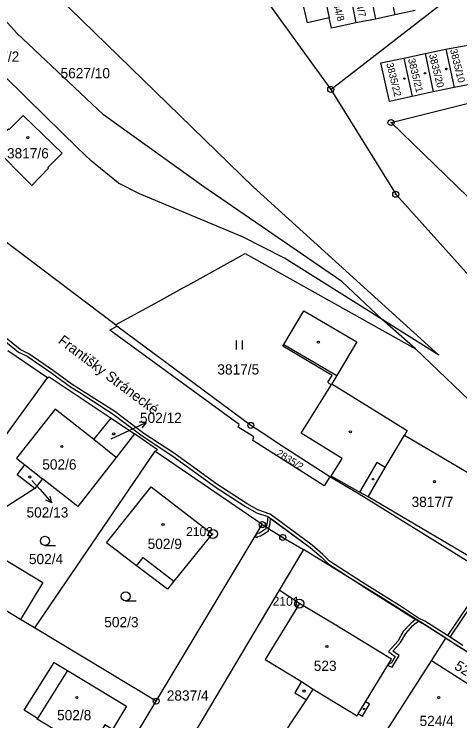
# Model space of a CAD drawing. Extents: x -644096 to -634268, y -1141430 to -1133463.
# Drawn here: x -640437.2 to -640363, y -1137748.7 to -1137631.3 of the extents above; entities that cross this region are included whole.
import ezdxf

# ---------------------------------------------------------------- set-up
doc = ezdxf.new("R2010")
doc.units = 0
for name, color, linetype in [('_CIVIL_CONSTRUCTION', 7, 'Continuous'), ('B_Hranice _3D', 7, 'Continuous'), ('M_Svah_Nasyp', 7, 'Continuous'), ('M_Svah_Zarez', 7, 'Continuous'), ('svrsek_osa_sjezdy', 7, 'Continuous'), ('svrsek_osa_VRT', 7, 'Continuous'), ('svrsek_popisy_VRT', 7, 'Continuous'), ('terminal_VRT', 7, 'Continuous')]:
    doc.layers.add(name, color=color, linetype=linetype)

msp = doc.modelspace()

# ---------------------------------------------------------------- linework, layer by layer
at = {"layer": '_CIVIL_CONSTRUCTION'}
for centre, radius in [((-640384.52, -1137643.83), 0.5), ((-640384.52, -1137643.83), 0.0303), ((-640374.49, -1137649.33), 0.5), ((-640374.49, -1137649.33), 0.0303), ((-640373.7, -1137661.25), 0.5), ((-640373.7, -1137661.25), 0.0303), ((-640397.8, -1137699.65), 0.5), ((-640397.8, -1137699.65), 0.0303), ((-640395.9, -1137716.14), 0.5), ((-640395.9, -1137716.14), 0.0303), ((-640404.11, -1137717.68), 0.75), ((-640404.11, -1137717.68), 0.03), ((-640392.5, -1137718.27), 0.5), ((-640392.5, -1137718.27), 0.0303), ((-640389.72, -1137729.25), 0.75), ((-640389.72, -1137729.25), 0.03), ((-640413.53, -1137745.46), 0.5), ((-640413.53, -1137745.46), 0.0303)]:
    msp.add_circle(centre, radius, dxfattribs=at)
at = {"layer": 'B_Hranice _3D'}
for points in [[(-640368.89, -1137732.19), (-640369.9, -1137731.68), (-640373.08, -1137729.6), (-640379.21, -1137725.75), (-640384.69, -1137722.23), (-640385.8, -1137721.09), (-640387.59, -1137719.54), (-640394.59, -1137714.42), (-640396.64, -1137713.7), (-640398.4, -1137712.7), (-640403.45, -1137709.42), (-640410.5, -1137704.33), (-640415.57, -1137700.99), (-640420.38, -1137697.37), (-640425.99, -1137693.79), (-640427.52, -1137692.83), (-640430.58, -1137690.58), (-640434.7, -1137687.75), (-640436.16, -1137687.06), (-640440.83, -1137683.28)], [(-640359.85, -1137726.8), (-640365.07, -1137734.54), (-640368.89, -1137732.19), (-640369.9, -1137731.68), (-640373.08, -1137729.6), (-640379.21, -1137725.75), (-640384.69, -1137722.23), (-640385.8, -1137721.09), (-640387.59, -1137719.54), (-640394.59, -1137714.42), (-640396.64, -1137713.7), (-640398.4, -1137712.7), (-640403.45, -1137709.42), (-640410.5, -1137704.33), (-640415.57, -1137700.99), (-640420.38, -1137697.37), (-640425.99, -1137693.79), (-640427.52, -1137692.83), (-640430.58, -1137690.58), (-640434.7, -1137687.75), (-640436.16, -1137687.06), (-640440.83, -1137683.28)], [(-640441.09, -1137683.72), (-640436.42, -1137687.48), (-640434.98, -1137688.17), (-640430.86, -1137691), (-640427.78, -1137693.25), (-640426.25, -1137694.21), (-640420.66, -1137697.79), (-640415.85, -1137701.41), (-640410.78, -1137704.75), (-640403.73, -1137709.84), (-640398.68, -1137713.12), (-640396.84, -1137714.16), (-640394.99, -1137714.77), (-640387.91, -1137719.92), (-640386.12, -1137721.47), (-640385.01, -1137722.61), (-640379.67, -1137726.04), (-640379.51, -1137726.14), (-640376.19, -1137728.19), (-640369.29, -1137732.49), (-640368.93, -1137732.72), (-640368.21, -1137733.19), (-640365.14, -1137735.09), (-640363.22, -1137736.37), (-640361.87, -1137737.21)], [(-640441.09, -1137683.72), (-640436.42, -1137687.48), (-640434.98, -1137688.17), (-640430.86, -1137691), (-640427.78, -1137693.25), (-640426.25, -1137694.21), (-640420.66, -1137697.79), (-640415.85, -1137701.41), (-640410.78, -1137704.75), (-640403.73, -1137709.84), (-640398.68, -1137713.12), (-640396.84, -1137714.16), (-640394.99, -1137714.77), (-640395.1, -1137715.86), (-640395.38, -1137716.9), (-640396.38, -1137717.54), (-640396.79, -1137717.62), (-640397.13, -1137718.18), (-640396.73, -1137718.26), (-640396.7, -1137718.11), (-640396.2, -1137718.02), (-640394.94, -1137717.22), (-640394.6, -1137715.94), (-640394.52, -1137715.09), (-640387.91, -1137719.92), (-640386.12, -1137721.47), (-640385.01, -1137722.61), (-640379.67, -1137726.04), (-640379.51, -1137726.14), (-640376.19, -1137728.19), (-640369.29, -1137732.49), (-640368.93, -1137732.72), (-640368.21, -1137733.19), (-640365.14, -1137735.09), (-640363.22, -1137736.37), (-640361.87, -1137737.21)], [(-640362.52, -1137736.23), (-640364.65, -1137734.81), (-640359.39, -1137727)], [(-640362.52, -1137736.23), (-640365.07, -1137734.54), (-640368.89, -1137732.19)]]:
    msp.add_lwpolyline(points, dxfattribs=at)
msp.add_lwpolyline([(-640379.47, -1137726.17), (-640373.34, -1137730.02), (-640370.43, -1137731.92), (-640371.19, -1137732.55), (-640372.44, -1137733.91), (-640373.29, -1137735.43), (-640374.92, -1137737.23), (-640373.81, -1137738.04), (-640374.49, -1137739.2), (-640374.75, -1137739.09), (-640375.01, -1137739.52), (-640374.27, -1137739.82), (-640373.15, -1137737.9), (-640374.18, -1137737.15), (-640372.89, -1137735.73), (-640372.04, -1137734.21), (-640370.85, -1137732.91), (-640369.98, -1137732.2), (-640369.11, -1137732.63)], close=True, dxfattribs=at)
at = {"layer": 'M_Svah_Nasyp'}
for p, q in [((-640392.32, -1137686.22), (-640383.52, -1137691.38)), ((-640384.33, -1137692.77), (-640384.45, -1137692.98)), ((-640375.45, -1137706.64), (-640372.24, -1137701.28)), ((-640376.85, -1137705.84), (-640379.71, -1137710.72)), ((-640378.27, -1137711.53), (-640375.45, -1137706.64)), ((-640375.45, -1137706.64), (-640376.85, -1137705.84)), ((-640384.67, -1137708.22), (-640384.43, -1137708.11)), ((-640416.78, -1137723), (-640415.7, -1137721.6)), ((-640415.7, -1137721.6), (-640410.58, -1137725.54)), ((-640428.27, -1137740.37), (-640433.24, -1137748.33)), ((-640389.38, -1137742.21), (-640387.44, -1137743.46)), ((-640379.93, -1137747.59), (-640378.71, -1137745.59))]:
    msp.add_line(p, q, dxfattribs=at)
at = {"layer": 'M_Svah_Zarez'}
for centre, radius in [((-640368.83, -1137641.14), 0.123), ((-640365.29, -1137640.43), 0.123), ((-640372.29, -1137642.03), 0.123), ((-640434.87, -1137651.84), 0.175), ((-640386.57, -1137685.81), 0.175), ((-640420.6, -1137701.07), 0.175), ((-640381.25, -1137700.73), 0.175), ((-640429.22, -1137703.16), 0.175), ((-640434.54, -1137708.22), 0.175), ((-640377.46, -1137708.6), 0.123), ((-640367.25, -1137709), 0.175), ((-640412.39, -1137716.13), 0.175), ((-640385.14, -1137736.39), 0.175), ((-640388.96, -1137743.78), 0.175), ((-640426.71, -1137744.87), 0.175), ((-640366.57, -1137744.87), 0.175), ((-640378.96, -1137746.75), 0.123)]:
    msp.add_circle(centre, radius, dxfattribs=at)
at = {"layer": 'svrsek_osa_sjezdy'}
for p, q in [((-640400.18, -1137687.05), (-640400.18, -1137685.55)), ((-640399.18, -1137687.05), (-640399.18, -1137685.55)), ((-640432.01, -1137719.58), (-640430.26, -1137719.58)), ((-640418.61, -1137728.81), (-640416.86, -1137728.81))]:
    msp.add_line(p, q, dxfattribs=at)
for centre in [(-640432.01, -1137718.83), (-640418.61, -1137728.06)]:
    msp.add_circle(centre, 0.75, dxfattribs=at)
at = {"layer": 'svrsek_popisy_VRT'}
for p, q in [((-640417.94, -1137700.43), (-640415.22, -1137699.16)), ((-640415.22, -1137699.16), (-640416.34, -1137699.13)), ((-640415.22, -1137699.16), (-640415.92, -1137700.04)), ((-640421.04, -1137701.91), (-640417.94, -1137700.43)), ((-640434.18, -1137708.82), (-640432.87, -1137710.26)), ((-640432.87, -1137710.26), (-640430.86, -1137712.49)), ((-640430.86, -1137712.49), (-640431.16, -1137711.41)), ((-640430.86, -1137712.49), (-640431.9, -1137712.08))]:
    msp.add_line(p, q, dxfattribs=at)
at = {"layer": 'terminal_VRT'}
for p, q in [((-640375.05, -1137625.59), (-640373.83, -1137631.46)), ((-640381.5, -1137627), (-640380.33, -1137632.78)), ((-640378.28, -1137626.29), (-640377.06, -1137632.16)), ((-640384.52, -1137643.83), (-640366.34, -1137629.76)), ((-640373.83, -1137631.46), (-640377.06, -1137632.16)), ((-640370.46, -1137630.72), (-640373.83, -1137631.46)), ((-640377.06, -1137632.16), (-640380.33, -1137632.78)), ((-640365.37, -1137637.13), (-640361.43, -1137636.41)), ((-640368.82, -1137637.89), (-640365.37, -1137637.13)), ((-640365.37, -1137637.13), (-640364, -1137643.51)), ((-640372.34, -1137638.63), (-640368.82, -1137637.89)), ((-640372.34, -1137638.63), (-640370.98, -1137645)), ((-640368.82, -1137637.89), (-640367.46, -1137644.25)), ((-640364, -1137643.51), (-640367.46, -1137644.25)), ((-640360.04, -1137642.75), (-640364, -1137643.51)), ((-640367.46, -1137644.25), (-640370.98, -1137645)), ((-640370.39, -1137686.93), (-640375.94, -1137682.07)), ((-640420.05, -1137683.15), (-640420.29, -1137682.97)), ((-640348.37, -1137708.04), (-640370.39, -1137686.93)), ((-640431.6, -1137691.76), (-640438.21, -1137687.24)), ((-640452.44, -1137720.38), (-640431.6, -1137691.76)), ((-640423.92, -1137702.01), (-640421.03, -1137698.44)), ((-640421.03, -1137698.44), (-640417.14, -1137701.05)), ((-640417.14, -1137701.05), (-640420.2, -1137704.97)), ((-640420.2, -1137704.97), (-640423.92, -1137702.01)), ((-640413.75, -1137703.95), (-640433.77, -1137733.29)), ((-640395.9, -1137716.14), (-640413.75, -1137703.95)), ((-640435.37, -1137706.2), (-640432.45, -1137708.52)), ((-640432.45, -1137708.52), (-640433.72, -1137710.16)), ((-640413.53, -1137745.46), (-640395.9, -1137716.14)), ((-640389.05, -1137720.27), (-640393.08, -1137727.04)), ((-640393.08, -1137727.04), (-640408.01, -1137752.08)), ((-640389.72, -1137729.25), (-640393.08, -1137727.04)), ((-640433.77, -1137733.29), (-640436.1, -1137731.89)), ((-640413.53, -1137745.46), (-640433.77, -1137733.29)), ((-640367.76, -1137738.75), (-640365.39, -1137735.02)), ((-640365.39, -1137735.02), (-640354.7, -1137741.67)), ((-640423.84, -1137762.61), (-640413.53, -1137745.46))]:
    msp.add_line(p, q, dxfattribs=at)
for points in [[(-640469.67, -1137590.5), (-640475.4, -1137581.27), (-640444.05, -1137613.62), (-640427.88, -1137630.4), (-640397.43, -1137660.02), (-640366.53, -1137687.97), (-640375.94, -1137682.07)], [(-640375.94, -1137682.07), (-640392.21, -1137671.87), (-640399.16, -1137668.35), (-640416.29, -1137661.19), (-640419.78, -1137659.42), (-640424.3, -1137655.75), (-640426.61, -1137653.52), (-640434.73, -1137645.59), (-640439.71, -1137640.72), (-640445.96, -1137646.97), (-640450.43, -1137642.6), (-640446.33, -1137638.27), (-640445.31, -1137635.54), (-640445.92, -1137633.09), (-640458.29, -1137608.82), (-640469.67, -1137590.5)], [(-640375.94, -1137682.07), (-640382.68, -1137675.72), (-640405.62, -1137660.04), (-640422.31, -1137648.07), (-640436.7, -1137634.46), (-640448.27, -1137621.61), (-640458.52, -1137607.8), (-640461.94, -1137597.43), (-640469.67, -1137590.5)], [(-640409.68, -1137617.66), (-640396.81, -1137627.22), (-640394.7, -1137629.8), (-640384.52, -1137643.83)], [(-640384.78, -1137631.93), (-640388.37, -1137632.76), (-640389.8, -1137626.55), (-640385.75, -1137625.64), (-640385.39, -1137627.63)], [(-640385.39, -1137627.63), (-640385.63, -1137627.72), (-640384.78, -1137631.93)], [(-640380.33, -1137632.78), (-640384.4, -1137633.66), (-640384.78, -1137631.93)], [(-640370.98, -1137645), (-640374.76, -1137645.83), (-640376.19, -1137639.44), (-640372.34, -1137638.63)], [(-640358.08, -1137665.24), (-640374.49, -1137649.33), (-640331.98, -1137638.7)], [(-640384.52, -1137643.83), (-640373.7, -1137661.25), (-640361.01, -1137675.36), (-640344.44, -1137691.51), (-640338.29, -1137696.16)], [(-640431.53, -1137656.83), (-640431.42, -1137656.94), (-640434.2, -1137659.77), (-640440.86, -1137653.17), (-640438.11, -1137650.39), (-640437.99, -1137650.51), (-640435.64, -1137648.14), (-640429.18, -1137654.43), (-640431.53, -1137656.83)], [(-640420.29, -1137682.97), (-640458.92, -1137653.8), (-640460.37, -1137652.71)], [(-640420.29, -1137682.97), (-640413.16, -1137679.05), (-640408.87, -1137676.69), (-640408.22, -1137676.33), (-640398.75, -1137671.12), (-640370.39, -1137686.93)], [(-640360.72, -1137721.87), (-640378.27, -1137711.53), (-640379.71, -1137710.72), (-640384.43, -1137708.11), (-640382.6, -1137705.16), (-640389.4, -1137700.93), (-640384.45, -1137692.98), (-640384.98, -1137692.46), (-640384.28, -1137691.37), (-640392.47, -1137686.49), (-640392.32, -1137686.22), (-640389.01, -1137680.64), (-640380.18, -1137685.78), (-640383.52, -1137691.38), (-640384.33, -1137692.77), (-640371.78, -1137700.51), (-640372.24, -1137701.28), (-640358.34, -1137709.45), (-640358.8, -1137710.21), (-640353.23, -1137713.49)], [(-640384.67, -1137708.22), (-640385.6, -1137709.67), (-640397.48, -1137702.16), (-640397.29, -1137701.53), (-640399.92, -1137699.95), (-640399.76, -1137699.52), (-640421.26, -1137683.85), (-640420.05, -1137683.15)], [(-640384.67, -1137708.22), (-640393.37, -1137702.61), (-640394.1, -1137702.1), (-640395.14, -1137701.41), (-640397.8, -1137699.65), (-640420.05, -1137683.15)], [(-640431.6, -1137691.76), (-640431.3, -1137691.59), (-640421.03, -1137698.44)], [(-640423.92, -1137702.01), (-640430.35, -1137696.93), (-640436.74, -1137705.12), (-640435.37, -1137706.2)], [(-640413.75, -1137703.95), (-640413.33, -1137703.72), (-640417.14, -1137701.05)], [(-640420.2, -1137704.97), (-640426.57, -1137713.1), (-640432.45, -1137708.52)], [(-640433.72, -1137710.16), (-640436.66, -1137707.86), (-640435.37, -1137706.2)], [(-640361.3, -1137722.52), (-640379.81, -1137711.07), (-640384.67, -1137708.22)], [(-640433.72, -1137710.16), (-640439.66, -1137713.91), (-640443.4, -1137719.1), (-640432.39, -1137725.78), (-640436.1, -1137731.89)], [(-640415.27, -1137724.16), (-640416.78, -1137723), (-640421.78, -1137719.14), (-640414.35, -1137709.87), (-640404.23, -1137717.69), (-640410.58, -1137725.54), (-640411.66, -1137726.85), (-640415.27, -1137724.16)], [(-640395.9, -1137716.14), (-640392.5, -1137718.27), (-640389.05, -1137720.27)], [(-640365.39, -1137735.02), (-640368.93, -1137732.72), (-640369.29, -1137732.49), (-640376.19, -1137728.19), (-640379.51, -1137726.14), (-640389.05, -1137720.27)], [(-640436.1, -1137731.89), (-640447.14, -1137725.25), (-640447.84, -1137724.83)], [(-640389.72, -1137729.25), (-640395.42, -1137738.53), (-640389.38, -1137742.21), (-640390.5, -1137744.07), (-640388.54, -1137745.26)], [(-640388.54, -1137745.26), (-640387.44, -1137743.46), (-640380.13, -1137747.93), (-640379.93, -1137747.59), (-640379.25, -1137747.98), (-640378.04, -1137745.99), (-640378.71, -1137745.59), (-640374.4, -1137738.51), (-640383.64, -1137732.84), (-640389.72, -1137729.25)], [(-640433.32, -1137748.46), (-640433.24, -1137748.33), (-640435.46, -1137746.99), (-640430.48, -1137739.02), (-640428.27, -1137740.37), (-640418.48, -1137746.32), (-640420.8, -1137750.17), (-640422.09, -1137749.39), (-640424.69, -1137753.69), (-640433.32, -1137748.46)], [(-640376.28, -1137752.05), (-640375.79, -1137751.29), (-640367.76, -1137738.75)], [(-640356.8, -1137745), (-640357.17, -1137744.76), (-640357.5, -1137745.28), (-640367.76, -1137738.75)], [(-640396.57, -1137753.71), (-640394.7, -1137754.89), (-640393.1, -1137752.31), (-640391.29, -1137749.42), (-640388.54, -1137745.26)]]:
    msp.add_lwpolyline(points, dxfattribs=at)

# ---------------------------------------------------------------- texts
at = {"layer": '_CIVIL_CONSTRUCTION'}
for s, p in [('2102', (-640408.56, -1137718.05)), ('2101', (-640394.17, -1137729.62))]:
    msp.add_text(s, height=1.5, dxfattribs=at).set_placement(p)
at = {"layer": 'svrsek_osa_VRT'}
for s, height, rotation, p in [('3834/7', 1.19, 285, (-640381.01, -1137627.25)), ('3834/8', 1.19, 285, (-640384.59, -1137627.93)), ('3835/10', 1.19, 284, (-640364.68, -1137637.24)), ('3835/21', 1.19, 284, (-640371.67, -1137638.83)), ('3835/20', 1.19, 284, (-640368.18, -1137638.06)), ('3835/22', 1.19, 284, (-640375.29, -1137639.55)), ('2835/2', 1.19, 328, (-640393.65, -1137704.57)), ('524/7', 1.7, 328, (-640364.09, -1137740.04))]:
    msp.add_text(s, height=height, rotation=rotation, dxfattribs=at).set_placement(p)
for s, p in [('5627/2', (-640443.25, -1137639.23)), ('5627/10', (-640429.43, -1137641.98)), ('3817/6', (-640438.34, -1137655.29)), ('3817/5', (-640403.36, -1137691.2)), ('502/12', (-640416.23, -1137699.25)), ('502/6', (-640432.47, -1137706.99)), ('3817/7', (-640371.07, -1137713.21)), ('502/13', (-640435.09, -1137714.96)), ('502/9', (-640414.95, -1137720.18)), ('502/4', (-640434.69, -1137722.7)), ('502/3', (-640422.16, -1137733.19)), ('523', (-640387.33, -1137740.44)), ('2837/4', (-640411.77, -1137745.38)), ('502/8', (-640430.01, -1137748.64)), ('524/4', (-640369.74, -1137749.59))]:
    msp.add_text(s, height=1.7, dxfattribs=at).set_placement(p)
at = {"layer": 'svrsek_popisy_VRT'}
msp.add_text('Františky Stránecké', height=1.7, rotation=323, dxfattribs=at).set_placement((-640429.96, -1137685.86))

doc.saveas('drawing.dxf')
